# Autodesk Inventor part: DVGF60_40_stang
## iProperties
Created: 2010-04
Part Number: DVGF60_40_stang
Document SubType Name: Modeling
Designer: TB
Mass: 374.959 g
Surface Area: 409.882 cm^2
Volume: 374.959 cm^3
Density: 1 g/cm^3
Author: TB
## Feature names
1. Revolution1
2. Fillet1
3. Revolution2
4. Extrusion1
5. Extrusion2
6. Extrusion3
7. Chamfer2
8. Chamfer3
9. Chamfer4
